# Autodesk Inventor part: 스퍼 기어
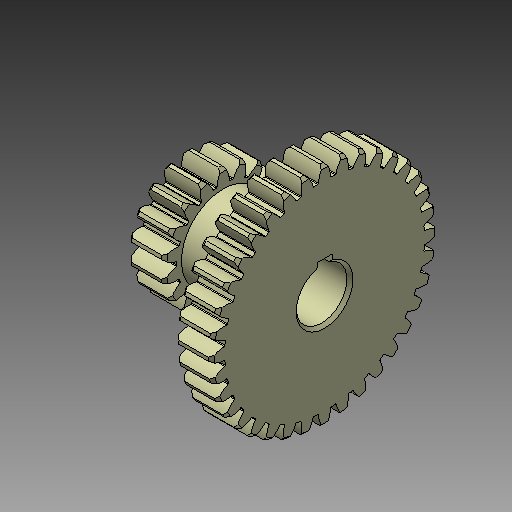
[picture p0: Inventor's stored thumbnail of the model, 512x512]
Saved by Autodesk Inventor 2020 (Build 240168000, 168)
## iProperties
Created: 2024-01
Part Number: 스퍼 기어
Material: 강철, 탄소
Document SubType Name: Modeling
Designer: mdu-01
Density: 1 g/cm^3
Appearance: 기본값(1)
Author: mdu-01
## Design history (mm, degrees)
sketch "스케치1"
  geometry: L1 (0, 0)-(46, 0); L2 (46, 9.5)-(46, 33.5); L3 (46, 33.5)-(34, 33.5); L4 (34, 33.5)-(34, 14); L5 (34, 14)-(12, 14); L6 (12, 14)-(12, 15.5); L7 (12, 15.5)-(0, 15.5); L8 (0, 15.5)-(0, 9.5); L9 (1, 8.5)-(45, 8.5); L10 (0, 9.5)-(1, 8.5); L11 (46, 9.5)-(45, 8.5); 4 further points
  constraints: 22 end point, 7 parallel, 7 point on line, 2 perpendicular, 1 horizontal
  dimensions: "d0" = 46 distance between parallel lines of L2 L8; "d2" = 36 diameter of point (0, 18) L1; "d3" = 2.5 distance from line of L7 point (0, 18); "d4" = 12 distance between parallel lines of L6 L8; "d5" = 28 diameter of L5 L1; "d6" = 17 diameter of L9 L1; "d7" = 72 diameter of point (46, 36) L1; "d9" = 2.5 distance from line of L3 point (46, 36); "d10" = 1 distance of L8.end point (0, 8.5); "d11" = 1 distance of L9.start point (0, 8.5) (= d10); "d12" = 1 distance of L2.start point (46, 8.5) (= d10); "d13" = 1 distance of L9.end point (46, 8.5) (= d12)
revolve "회전1" sketch "스케치1" stored, may be unused: angle "d14" = 90 deg
sketch "스케치2" dims "d15" = 2.5
  geometry: L1 (0, 0)-(0, 20); A1 r 20 centre (0, 0) between (0.57, 19.992) and (-0.57, 19.992); A2 r 9.478 centre (-7.394, 14.854) between (2.07, 15.361) and (0.57, 19.992); A3 r 9.478 centre (7.394, 14.854) between (-0.57, 19.992) and (-2.07, 15.361); A4 r 15.5 centre (0, 0) between (2.07, 15.361) and (-2.07, 15.361); 2 further points
  constraints: 10 point on circle, 4 centre point, 3 symmetric about line, 2 end point, 1 coincident, 1 vertical, 6 other
  dimensions: "d16" = 2 dimension on A1; "d17" = 1.57 distance from line of point (1.57, 17.931) L1; "d18" = 1 horizontal distance of A1.start point (1.57, 17.931); "d19" = 0.5 horizontal distance of A2.start point (1.57, 17.931)
extrude "돌출1" join sketch "스케치2" stored distance "d20" = 10; taper "d21" = 0 deg
chamfer "모따기1" distance "d22" = 1; stored, may be unused: second distance "d23" = 2, angle "d24" = 45 deg
fillet "모깎기1" dims "d25" = 0.25
sketch "스케치3" dims "d29" = 2.5
  geometry: L1 (0, 0)-(0, 38); A1 r 38 centre (0, 0) between (0.57, 37.996) and (-0.57, 37.996); A2 r 9.246 centre (-7.162, 32.926) between (2.07, 33.436) and (0.57, 37.996); A3 r 9.246 centre (7.162, 32.926) between (-0.57, 37.996) and (-2.07, 33.436); A4 r 33.5 centre (0, 0) between (2.07, 33.436) and (-2.07, 33.436); 2 further points
  constraints: 10 point on circle, 4 centre point, 3 symmetric about line, 2 coincident, 2 end point, 1 vertical, 6 other
  dimensions: "d30" = 2 dimension on A1; "d31" = 1.57 distance from line of point (1.57, 35.966) L1; "d32" = 0.5 horizontal distance of A2.start point (1.57, 35.966); "d33" = 1 horizontal distance of A1.start point (1.57, 35.966)
extrude "돌출2" join sketch "스케치3" stored distance "d34" = 0; taper "d35" = 0 deg
chamfer "모따기2" distance "d36" = 1; stored, may be unused: second distance "d37" = 2, angle "d38" = 45 deg
fillet "모깎기2" dims "d39" = 0.25
sketch "스케치4"
  geometry: L1 (-2.5, 8.124)-(2.5, 8.124); L2 (2.5, 8.124)-(2.5, 10.8); L3 (2.5, 10.8)-(-2.5, 10.8); L4 (-2.5, 10.8)-(-2.5, 8.124); A1 r 8.5 centre (0, 0) between (-2.5, 8.124) and (2.5, 8.124) reference; 2 further points
  constraints: 8 end point, 3 point on circle, 2 parallel, 1 horizontal, 1 perpendicular, 1 vertical alignment
  dimensions: "d43" = 5 distance between parallel lines of L2 L4; "d45" = 19.3 distance from line of point (0, -8.5) L3
extrude "돌출3" cut sketch "스케치4" extent not by distance; stored distance "d46" = 10; taper "d47" = 0 deg
node "솔리드1"
pattern_circular "원형 패턴1" dims angle "d27" = 360 deg
pattern_circular "원형 패턴2" dims angle "d41" = 360 deg
